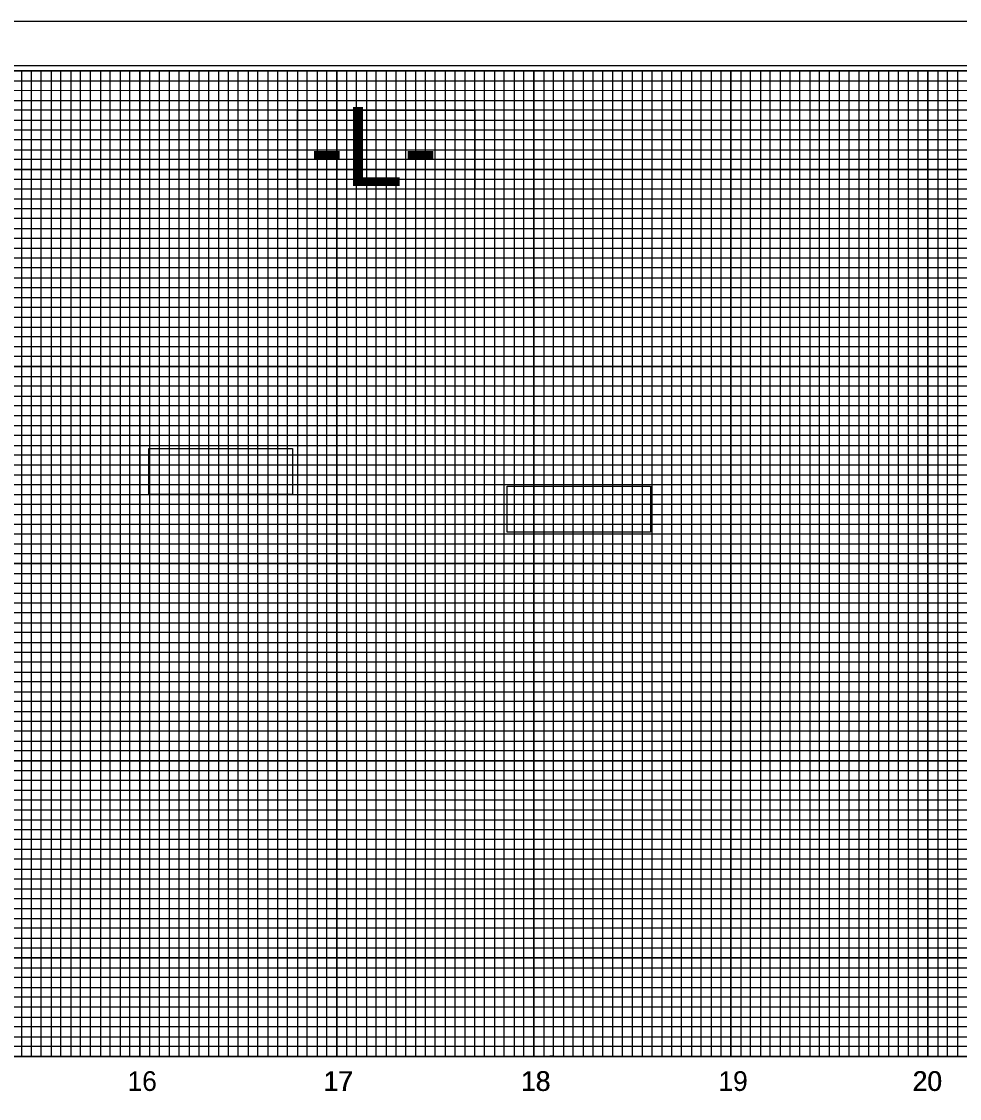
# Model space of a CAD drawing. Extents: x 1779926 to 1781610, y 620464 to 621564.
# Drawn here: x 1780683 to 1781159, y 621018 to 621564 of the extents above; entities that cross this region are included whole.
import ezdxf

# ---------------------------------------------------------------- set-up
doc = ezdxf.new("R2010")
doc.units = 0
for name, color, linetype in [('Exist Vertical Profile Horizontal Axis Label Major', 7, 'Continuous'), ('Exist Vertical Profile Vertical Axis Label', 7, 'Continuous'), ('Prop Grid Mask', 7, 'Continuous'), ('Scratch_Level_0', 7, 'Continuous'), ('Sheet Cutting Line CELL', 7, 'Continuous'), ('Sheet DOT Grid CELL', 7, 'Continuous'), ('Sheet Layout Profile Border Port 1', 7, 'Continuous'), ('Sheet Plot Border Inside CELL', 7, 'Continuous'), ('Sheet Plot Border Outside CELL', 7, 'Continuous'), ('Sheet Profile CELL', 7, 'Continuous'), ('Sheet Profile Grid Major CELL', 7, 'Continuous'), ('Sheet Profile Grid Middle CELL', 7, 'Continuous'), ('Sheet Profile Grid Minor CELL', 7, 'Continuous')]:
    doc.layers.add(name, color=color, linetype=linetype)

msp = doc.modelspace()

# ---------------------------------------------------------------- linework, layer by layer
at = {"layer": 'Prop Grid Mask'}
for points in [[(1780822.96, 621519.19), (1780912.96, 621519.19), (1780912.96, 621479.19), (1780822.96, 621479.19)], [(1780747.63, 621347.57), (1780820.48, 621347.57), (1780820.48, 621324.2), (1780747.63, 621324.2)], [(1780929.38, 621328.54), (1781002.23, 621328.54), (1781002.23, 621305.18), (1780929.38, 621305.18)]]:
    msp.add_lwpolyline(points, close=True, dxfattribs=at)
at = {"layer": 'Scratch_Level_0'}
msp.add_lwpolyline([(1780142.96, 621039.18), (1780142.96, 621239.19), (1780092.96, 621239.19), (1780092.96, 621264.19), (1780142.96, 621289.19), (1780142.96, 621539.18), (1781392.96, 621539.18), (1781392.96, 621314.18), (1781542.96, 621314.18), (1781542.96, 621039.18)], close=True, dxfattribs=at)
at = {"layer": 'Sheet Cutting Line CELL'}
msp.add_line((1781609.96, 621564.19), (1779925.96, 621564.19), dxfattribs=at)
at = {"layer": 'Sheet DOT Grid CELL'}
for p, q in [((1780692.96, 621039.19), (1780692.96, 621539.19)), ((1780742.96, 621039.19), (1780742.96, 621539.19)), ((1780792.96, 621039.19), (1780792.96, 621539.19)), ((1780842.96, 621039.19), (1780842.96, 621539.19)), ((1780892.96, 621039.19), (1780892.96, 621539.19)), ((1780942.96, 621039.19), (1780942.96, 621539.19)), ((1780992.96, 621039.19), (1780992.96, 621539.19)), ((1781042.96, 621039.19), (1781042.96, 621539.19)), ((1781092.96, 621039.19), (1781092.96, 621539.19)), ((1781142.96, 621039.19), (1781142.96, 621539.19)), ((1781392.91, 621489.19), (1780092.96, 621489.19)), ((1781392.91, 621439.19), (1780092.96, 621439.19)), ((1781392.96, 621389.19), (1780092.96, 621389.19)), ((1781392.91, 621339.19), (1780092.96, 621339.19)), ((1781592.96, 621289.19), (1780092.96, 621289.19)), ((1781592.96, 621239.19), (1780092.96, 621239.19)), ((1781592.96, 621189.19), (1780092.96, 621189.19)), ((1781592.96, 621139.19), (1780092.96, 621139.19)), ((1781592.96, 621089.19), (1780092.96, 621089.19))]:
    msp.add_line(p, q, dxfattribs=at)
at = {"layer": 'Sheet Layout Profile Border Port 1'}
msp.add_lwpolyline([(1780142.96, 621378.14), (1780142.96, 621039.19), (1781542.96, 621039.19), (1781542.96, 621314.19)], dxfattribs=at)
at = {"layer": 'Sheet Plot Border Inside CELL'}
msp.add_lwpolyline([(1779938.96, 620486.64), (1781605.46, 620486.64), (1781605.46, 621541.74), (1779938.96, 621541.74)], close=True, dxfattribs=at)
at = {"layer": 'Sheet Plot Border Outside CELL'}
msp.add_lwpolyline([(1779925.96, 620464.19), (1781609.96, 620464.19), (1781609.96, 621564.19), (1779925.96, 621564.19)], close=True, dxfattribs=at)
at = {"layer": 'Sheet Profile CELL'}
msp.add_line((1780092.96, 621039.19), (1781592.96, 621039.19), dxfattribs=at)
msp.add_lwpolyline([(1781592.96, 621539.19), (1780092.96, 621539.19), (1780092.96, 620489.19), (1781592.96, 620489.19)], close=True, dxfattribs=at)
at = {"layer": 'Sheet Profile Grid Major CELL'}
for points in [[(1780642.96, 621039.19), (1780692.96, 621039.19), (1780692.96, 621539.19), (1780742.96, 621539.19), (1780742.96, 621039.19), (1780792.96, 621039.19), (1780792.96, 621539.19), (1780842.96, 621539.19), (1780842.96, 621039.19), (1780892.96, 621039.19), (1780892.96, 621539.19), (1780942.96, 621539.19), (1780942.96, 621039.19), (1780992.96, 621039.19), (1780992.96, 621539.19), (1781042.96, 621539.19), (1781042.96, 621039.19), (1781092.96, 621039.19), (1781092.96, 621539.19), (1781142.96, 621539.19), (1781142.96, 621039.19), (1781192.96, 621039.19)], [(1780092.96, 621489.19), (1781392.96, 621489.19)], [(1781392.96, 621439.19), (1780092.96, 621439.19), (1780092.96, 621389.19), (1781392.96, 621389.19)], [(1781392.91, 621339.19), (1780092.96, 621339.19), (1780092.96, 621289.19), (1781592.96, 621289.19)], [(1781592.96, 621239.19), (1780092.96, 621239.19), (1780092.96, 621189.19), (1781592.96, 621189.19)], [(1781592.96, 621139.19), (1780092.96, 621139.19), (1780092.96, 621139.19), (1780092.96, 621089.19), (1781592.96, 621089.19)]]:
    msp.add_lwpolyline(points, dxfattribs=at)
at = {"layer": 'Sheet Profile Grid Middle CELL'}
msp.add_line((1780092.96, 621514.19), (1781392.91, 621514.19), dxfattribs=at)
for points in [[(1780667.96, 621039.19), (1780717.96, 621039.19), (1780717.96, 621039.19), (1780717.96, 621539.19), (1780767.96, 621539.19), (1780767.96, 621039.19), (1780817.96, 621039.19), (1780817.96, 621539.19), (1780867.96, 621539.19), (1780867.96, 621039.19), (1780917.96, 621039.19), (1780917.96, 621539.19), (1780967.96, 621539.19), (1780967.96, 621039.19), (1781017.96, 621039.19), (1781017.96, 621539.19), (1781067.96, 621539.19), (1781067.96, 621039.19), (1781117.96, 621039.19), (1781117.96, 621539.19), (1781167.96, 621539.19)], [(1781392.96, 621464.19), (1780092.96, 621464.19), (1780092.96, 621414.19), (1781392.96, 621414.19)], [(1781392.91, 621364.19), (1780092.96, 621364.19), (1780092.96, 621314.19), (1781417.96, 621314.19)], [(1781592.96, 621264.19), (1780092.96, 621264.19), (1780092.96, 621214.19), (1781592.96, 621214.19)], [(1781592.96, 621164.19), (1780092.96, 621164.19), (1780092.96, 621114.19), (1781592.96, 621114.19)], [(1781592.96, 621064.19), (1780092.96, 621064.19)]]:
    msp.add_lwpolyline(points, dxfattribs=at)
at = {"layer": 'Sheet Profile Grid Minor CELL'}
for p, q in [((1780142.96, 621534.19), (1781392.96, 621534.19)), ((1781392.96, 621529.19), (1780142.96, 621528.84)), ((1780142.96, 621524.19), (1781392.96, 621524.19)), ((1781392.91, 621404.19), (1780142.96, 621404.19)), ((1781392.96, 621399.19), (1780142.96, 621399.19)), ((1781392.96, 621394.19), (1780142.96, 621394.19)), ((1780142.96, 621384.19), (1781392.96, 621384.19)), ((1781392.96, 621379.19), (1780142.96, 621379.19)), ((1780142.96, 621374.19), (1781392.96, 621374.19)), ((1781392.96, 621354.19), (1780142.96, 621354.19)), ((1780142.96, 621349.19), (1781392.96, 621349.19)), ((1781392.91, 621329.19), (1780142.96, 621329.19)), ((1780142.96, 621324.19), (1781392.91, 621324.19)), ((1781542.96, 621304.19), (1780142.96, 621304.19)), ((1780142.96, 621299.19), (1781542.96, 621299.19)), ((1781542.96, 621294.19), (1780142.96, 621294.19)), ((1780142.96, 621284.19), (1781542.96, 621284.19)), ((1781542.96, 621279.19), (1780142.96, 621279.19)), ((1780142.96, 621274.19), (1781542.96, 621274.19)), ((1781542.96, 621269.19), (1780142.96, 621269.19)), ((1780142.96, 621259.19), (1781542.96, 621259.19)), ((1781542.96, 621254.19), (1780142.96, 621254.19)), ((1780142.96, 621249.19), (1781542.96, 621249.19)), ((1781542.96, 621244.19), (1780142.96, 621244.19)), ((1780142.96, 621234.19), (1781542.96, 621234.19)), ((1781542.96, 621229.19), (1780142.96, 621229.19)), ((1780142.96, 621224.19), (1781542.96, 621224.19)), ((1781542.96, 621219.19), (1780142.96, 621219.19)), ((1780142.96, 621209.19), (1781542.96, 621209.19)), ((1781542.96, 621204.19), (1780142.96, 621204.19)), ((1780142.96, 621199.19), (1781542.96, 621199.19)), ((1781542.96, 621194.19), (1780142.96, 621194.19)), ((1780142.96, 621184.19), (1781542.96, 621184.19)), ((1781542.96, 621179.19), (1780142.96, 621179.19)), ((1780142.96, 621174.19), (1781542.96, 621174.19)), ((1781542.96, 621169.19), (1780142.96, 621169.19)), ((1780142.96, 621159.19), (1781542.96, 621159.19)), ((1781542.96, 621154.19), (1780142.96, 621154.19)), ((1781542.96, 621149.19), (1780142.96, 621149.19)), ((1781542.96, 621144.19), (1780142.96, 621144.19)), ((1780142.96, 621134.19), (1781542.96, 621134.19)), ((1781542.96, 621129.19), (1780142.96, 621129.19)), ((1780142.96, 621124.19), (1781542.96, 621124.19)), ((1781542.96, 621119.19), (1780142.96, 621119.19)), ((1780142.96, 621109.19), (1781542.96, 621109.19)), ((1781542.96, 621104.19), (1780142.96, 621104.19)), ((1780142.96, 621099.19), (1781542.96, 621099.19)), ((1781542.96, 621094.19), (1780142.96, 621094.19)), ((1780142.96, 621084.19), (1781542.96, 621084.19)), ((1781542.96, 621079.19), (1780142.96, 621079.19)), ((1780142.96, 621074.19), (1781542.96, 621074.19)), ((1781542.96, 621069.19), (1780142.96, 621069.19)), ((1780142.96, 621059.19), (1781542.96, 621059.19)), ((1781542.96, 621054.19), (1780142.96, 621054.19)), ((1780142.96, 621049.19), (1781542.96, 621049.19))]:
    msp.add_line(p, q, dxfattribs=at)
for points in [[(1780677.96, 621539.19), (1780682.96, 621539.19), (1780682.96, 621039.19), (1780687.96, 621039.19), (1780687.96, 621539.19), (1780697.96, 621539.19), (1780697.96, 621039.19), (1780702.96, 621039.19), (1780702.96, 621539.19), (1780707.96, 621539.19), (1780707.96, 621039.19), (1780712.96, 621039.19), (1780712.96, 621539.19), (1780722.96, 621539.19), (1780722.96, 621039.19), (1780727.96, 621039.19), (1780727.96, 621539.19), (1780732.96, 621539.19), (1780732.96, 621039.19), (1780737.96, 621039.19), (1780737.96, 621539.19), (1780747.96, 621539.19), (1780747.96, 621039.19), (1780752.96, 621039.19), (1780752.96, 621539.19), (1780757.96, 621539.19), (1780757.96, 621039.19), (1780762.96, 621039.19), (1780762.96, 621539.19), (1780772.96, 621539.19), (1780772.96, 621039.19), (1780777.96, 621039.19), (1780777.96, 621539.19), (1780782.96, 621539.19), (1780782.96, 621039.19), (1780787.96, 621039.19), (1780787.96, 621539.19), (1780797.96, 621539.19), (1780797.96, 621039.19), (1780797.96, 621039.19), (1780802.96, 621039.19), (1780802.96, 621539.19), (1780807.96, 621539.19), (1780807.96, 621039.19), (1780812.96, 621039.19), (1780812.96, 621539.19), (1780822.96, 621539.19), (1780822.96, 621039.19), (1780827.96, 621039.19), (1780827.96, 621539.19), (1780832.96, 621539.19), (1780832.96, 621039.19), (1780837.96, 621039.19), (1780837.96, 621539.19), (1780847.96, 621539.19), (1780847.96, 621039.19), (1780852.96, 621039.19), (1780852.96, 621539.19), (1780857.96, 621539.19), (1780857.96, 621039.19), (1780862.96, 621039.19), (1780862.96, 621539.19), (1780872.96, 621539.19), (1780872.96, 621039.19), (1780877.96, 621039.19), (1780877.96, 621539.19), (1780882.96, 621539.19), (1780882.96, 621039.19), (1780887.96, 621039.19), (1780887.96, 621539.19), (1780897.96, 621539.19), (1780897.96, 621039.19), (1780902.96, 621039.19), (1780902.96, 621539.19), (1780907.96, 621539.19), (1780907.96, 621039.19), (1780912.96, 621039.19), (1780912.96, 621539.19), (1780922.96, 621539.19), (1780922.96, 621039.19), (1780927.96, 621039.19), (1780927.96, 621539.19), (1780932.96, 621539.19), (1780932.96, 621039.19), (1780937.96, 621039.19), (1780937.96, 621539.19), (1780947.96, 621539.19), (1780947.96, 621039.19), (1780952.66, 621039.74), (1780952.96, 621039.19), (1780952.96, 621539.19), (1780957.96, 621539.19), (1780957.96, 621039.19), (1780962.96, 621039.19), (1780962.96, 621539.19), (1780972.96, 621539.19), (1780972.96, 621039.19), (1780977.96, 621039.19)], [(1780977.96, 621039.19), (1780977.96, 621539.19), (1780982.96, 621539.19), (1780982.96, 621039.19), (1780987.96, 621039.19), (1780987.96, 621539.19), (1780997.96, 621539.19), (1780997.96, 621039.19), (1781002.96, 621039.19), (1781002.96, 621539.19), (1781007.96, 621539.19), (1781007.96, 621039.19), (1781012.96, 621039.19), (1781012.96, 621539.19), (1781022.96, 621539.19), (1781022.96, 621039.19), (1781027.96, 621039.19), (1781027.96, 621539.19), (1781032.96, 621539.19), (1781032.96, 621039.19), (1781037.96, 621039.19), (1781037.96, 621539.19), (1781047.96, 621539.19), (1781047.96, 621039.19), (1781052.96, 621039.19), (1781052.96, 621539.19), (1781057.96, 621539.19), (1781057.96, 621039.19), (1781062.96, 621039.19), (1781062.96, 621539.19), (1781072.96, 621539.19), (1781072.96, 621039.19), (1781077.96, 621039.19), (1781077.96, 621539.19), (1781082.96, 621539.19), (1781082.96, 621039.19), (1781087.96, 621039.19), (1781087.96, 621539.19), (1781097.96, 621539.19), (1781097.96, 621039.19), (1781102.96, 621039.19), (1781102.96, 621539.19), (1781107.96, 621539.19), (1781107.96, 621039.19), (1781112.96, 621039.19), (1781112.96, 621539.19), (1781122.96, 621539.19), (1781122.96, 621039.19), (1781127.96, 621039.19), (1781127.96, 621539.19), (1781132.96, 621539.19), (1781132.96, 621039.19), (1781137.96, 621039.19), (1781137.96, 621539.19), (1781147.96, 621539.19), (1781147.96, 621039.19), (1781152.96, 621039.19), (1781152.96, 621539.19), (1781157.96, 621539.19), (1781157.96, 621039.19), (1781162.96, 621039.19)], [(1781392.96, 621519.19), (1780142.96, 621519.19), (1780142.96, 621509.19), (1781392.96, 621509.19)], [(1781392.91, 621504.19), (1780142.96, 621504.19), (1780142.96, 621499.19), (1781392.96, 621499.19)], [(1781392.96, 621494.19), (1780142.96, 621494.19), (1780142.96, 621484.19), (1781392.96, 621484.19)], [(1781392.96, 621479.19), (1780142.96, 621479.19), (1780142.96, 621474.19), (1781392.96, 621474.19)], [(1781392.96, 621469.19), (1780142.96, 621469.19), (1780142.96, 621459.19), (1781392.96, 621459.19)], [(1781392.96, 621454.19), (1780142.96, 621454.19), (1780142.96, 621449.19), (1781392.96, 621449.19)], [(1781392.96, 621444.19), (1780142.96, 621444.19), (1780142.96, 621434.19), (1781392.96, 621434.19)], [(1781392.96, 621429.09), (1780143.06, 621429.09), (1780143.06, 621424.19), (1781392.96, 621424.19)], [(1781392.96, 621419.19), (1780142.96, 621419.19), (1780142.96, 621409.19), (1781392.96, 621409.19)], [(1781392.91, 621369.19), (1780142.96, 621369.19), (1780142.96, 621359.19), (1781392.91, 621359.19)], [(1781392.91, 621344.19), (1780142.96, 621344.19), (1780142.96, 621334.19), (1781392.91, 621334.19)], [(1781392.91, 621319.19), (1780142.96, 621319.19), (1780142.96, 621309.19), (1781542.96, 621309.19)], [(1781542.96, 621044.19), (1780142.96, 621044.19)]]:
    msp.add_lwpolyline(points, dxfattribs=at)

# ---------------------------------------------------------------- texts
at = {"layer": 'Exist Vertical Profile Horizontal Axis Label Major'}
for s, p in [('16', (1780736.76, 621021.69)), ('17', (1780836.18, 621021.69)), ('17', (1780836.18, 621021.69)), ('17', (1780836.5, 621021.69)), ('18', (1780936.4, 621021.69)), ('18', (1780936.4, 621021.69)), ('18', (1780936.63, 621021.69)), ('19', (1781036.63, 621021.69)), ('19', (1781036.63, 621021.69)), ('19', (1781036.67, 621021.69)), ('20', (1781135.13, 621021.69)), ('20', (1781135.13, 621021.69)), ('20', (1781135.35, 621021.69))]:
    msp.add_text(s, height=10, dxfattribs=at).set_placement(p)
at = {"layer": 'Exist Vertical Profile Vertical Axis Label'}
msp.add_text('-L-', height=40, dxfattribs=at).set_placement((1780829.02, 621480.78))

doc.saveas('drawing.dxf')
